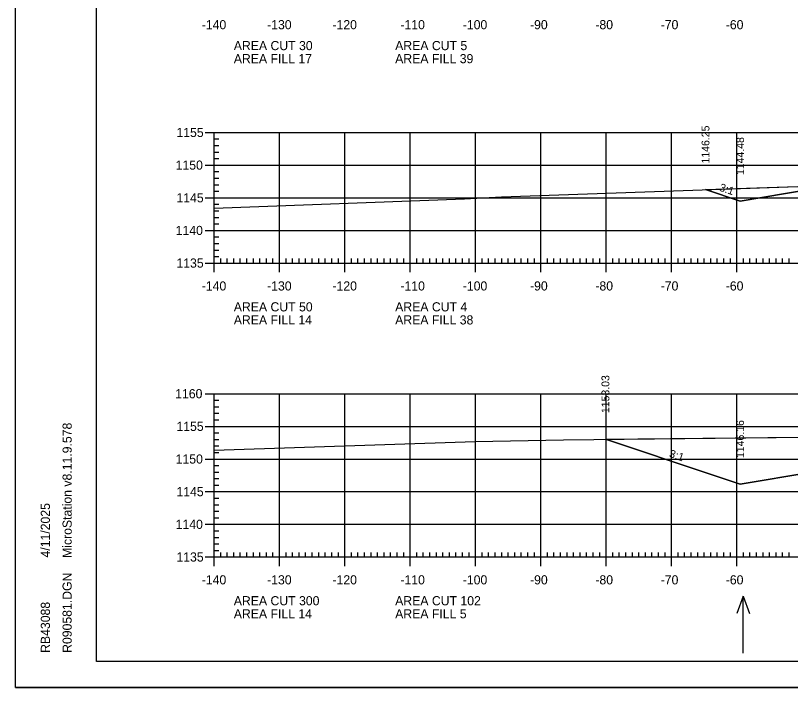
# Model space of a CAD drawing. Extents: x 1322838 to 1324533, y 339903 to 351025.
# Drawn here: x 1323533.3 to 1323651.9, y 342676.5 to 342779.4 of the extents above; entities that cross this region are included whole.
import ezdxf

# ---------------------------------------------------------------- set-up
doc = ezdxf.new("R2010")
doc.units = 0
for name, color, linetype in [('R_Axis', 7, 'Continuous'), ('R_Axis Annot', 7, 'Continuous'), ('R_Border', 7, 'Continuous'), ('R_Exist Surface', 7, 'Continuous'), ('R_Fin Surface', 7, 'Continuous'), ('R_Fin Surface Annot', 7, 'Continuous'), ('R_Grid', 7, 'Continuous'), ('R_No Plot', 7, 'Continuous'), ('R_Water Annot', 7, 'Continuous')]:
    doc.layers.add(name, color=color, linetype=linetype)

msp = doc.modelspace()

# ---------------------------------------------------------------- linework, layer by layer
at = {"layer": 'R_Axis'}
for p, q in [((1323562.32, 342761.5), (1323565.12, 342761.5)), ((1323563.72, 342741.5), (1323563.72, 342761.5)), ((1323563.72, 342760.5), (1323564.42, 342760.5)), ((1323563.72, 342759.5), (1323564.42, 342759.5)), ((1323563.72, 342758.5), (1323564.42, 342758.5)), ((1323563.72, 342757.5), (1323564.42, 342757.5)), ((1323562.32, 342756.5), (1323565.12, 342756.5)), ((1323563.72, 342755.5), (1323564.42, 342755.5)), ((1323563.72, 342754.5), (1323564.42, 342754.5)), ((1323563.72, 342753.5), (1323564.42, 342753.5)), ((1323563.72, 342752.5), (1323564.42, 342752.5)), ((1323562.32, 342751.5), (1323565.12, 342751.5)), ((1323563.72, 342750.5), (1323564.42, 342750.5)), ((1323563.72, 342749.5), (1323564.42, 342749.5)), ((1323563.72, 342748.5), (1323564.42, 342748.5)), ((1323562.32, 342746.5), (1323565.12, 342746.5)), ((1323563.72, 342747.5), (1323564.42, 342747.5)), ((1323563.72, 342745.5), (1323564.42, 342745.5)), ((1323563.72, 342744.5), (1323564.42, 342744.5)), ((1323563.72, 342743.5), (1323564.42, 342743.5)), ((1323563.72, 342740.1), (1323563.72, 342742.9)), ((1323573.72, 342740.1), (1323573.72, 342742.9)), ((1323583.72, 342740.1), (1323583.72, 342742.9)), ((1323593.72, 342740.1), (1323593.72, 342742.9)), ((1323603.72, 342740.1), (1323603.72, 342742.9)), ((1323613.72, 342740.1), (1323613.72, 342742.9)), ((1323623.72, 342740.1), (1323623.72, 342742.9)), ((1323633.72, 342740.1), (1323633.72, 342742.9)), ((1323643.72, 342740.1), (1323643.72, 342742.9)), ((1323563.72, 342742.5), (1323564.42, 342742.5)), ((1323564.72, 342741.5), (1323564.72, 342742.2)), ((1323565.72, 342741.5), (1323565.72, 342742.2)), ((1323566.72, 342741.5), (1323566.72, 342742.2)), ((1323567.72, 342741.5), (1323567.72, 342742.2)), ((1323568.72, 342741.5), (1323568.72, 342742.2)), ((1323569.72, 342741.5), (1323569.72, 342742.2)), ((1323570.72, 342741.5), (1323570.72, 342742.2)), ((1323571.72, 342741.5), (1323571.72, 342742.2)), ((1323572.72, 342741.5), (1323572.72, 342742.2)), ((1323574.72, 342741.5), (1323574.72, 342742.2)), ((1323575.72, 342741.5), (1323575.72, 342742.2)), ((1323576.72, 342741.5), (1323576.72, 342742.2)), ((1323577.72, 342741.5), (1323577.72, 342742.2)), ((1323578.72, 342741.5), (1323578.72, 342742.2)), ((1323579.72, 342741.5), (1323579.72, 342742.2)), ((1323580.72, 342741.5), (1323580.72, 342742.2)), ((1323581.72, 342741.5), (1323581.72, 342742.2)), ((1323582.72, 342741.5), (1323582.72, 342742.2)), ((1323584.72, 342741.5), (1323584.72, 342742.2)), ((1323585.72, 342741.5), (1323585.72, 342742.2)), ((1323586.72, 342741.5), (1323586.72, 342742.2)), ((1323587.72, 342741.5), (1323587.72, 342742.2)), ((1323588.72, 342741.5), (1323588.72, 342742.2)), ((1323589.72, 342741.5), (1323589.72, 342742.2)), ((1323590.72, 342741.5), (1323590.72, 342742.2)), ((1323591.72, 342741.5), (1323591.72, 342742.2)), ((1323592.72, 342741.5), (1323592.72, 342742.2)), ((1323594.72, 342741.5), (1323594.72, 342742.2)), ((1323595.72, 342741.5), (1323595.72, 342742.2)), ((1323596.72, 342741.5), (1323596.72, 342742.2)), ((1323597.72, 342741.5), (1323597.72, 342742.2)), ((1323598.72, 342741.5), (1323598.72, 342742.2)), ((1323599.72, 342741.5), (1323599.72, 342742.2)), ((1323600.72, 342741.5), (1323600.72, 342742.2)), ((1323601.72, 342741.5), (1323601.72, 342742.2)), ((1323602.72, 342741.5), (1323602.72, 342742.2)), ((1323604.72, 342741.5), (1323604.72, 342742.2)), ((1323605.72, 342741.5), (1323605.72, 342742.2)), ((1323606.72, 342741.5), (1323606.72, 342742.2)), ((1323607.72, 342741.5), (1323607.72, 342742.2)), ((1323608.72, 342741.5), (1323608.72, 342742.2)), ((1323609.72, 342741.5), (1323609.72, 342742.2)), ((1323610.72, 342741.5), (1323610.72, 342742.2)), ((1323611.72, 342741.5), (1323611.72, 342742.2)), ((1323612.72, 342741.5), (1323612.72, 342742.2)), ((1323614.72, 342741.5), (1323614.72, 342742.2)), ((1323615.72, 342741.5), (1323615.72, 342742.2)), ((1323616.72, 342741.5), (1323616.72, 342742.2)), ((1323617.72, 342741.5), (1323617.72, 342742.2)), ((1323618.72, 342741.5), (1323618.72, 342742.2)), ((1323619.72, 342741.5), (1323619.72, 342742.2)), ((1323620.72, 342741.5), (1323620.72, 342742.2)), ((1323621.72, 342741.5), (1323621.72, 342742.2)), ((1323622.72, 342741.5), (1323622.72, 342742.2)), ((1323624.72, 342741.5), (1323624.72, 342742.2)), ((1323625.72, 342741.5), (1323625.72, 342742.2)), ((1323626.72, 342741.5), (1323626.72, 342742.2)), ((1323627.72, 342741.5), (1323627.72, 342742.2)), ((1323628.72, 342741.5), (1323628.72, 342742.2)), ((1323629.72, 342741.5), (1323629.72, 342742.2)), ((1323630.72, 342741.5), (1323630.72, 342742.2)), ((1323631.72, 342741.5), (1323631.72, 342742.2)), ((1323632.72, 342741.5), (1323632.72, 342742.2)), ((1323634.72, 342741.5), (1323634.72, 342742.2)), ((1323635.72, 342741.5), (1323635.72, 342742.2)), ((1323636.72, 342741.5), (1323636.72, 342742.2)), ((1323637.72, 342741.5), (1323637.72, 342742.2)), ((1323638.72, 342741.5), (1323638.72, 342742.2)), ((1323639.72, 342741.5), (1323639.72, 342742.2)), ((1323640.72, 342741.5), (1323640.72, 342742.2)), ((1323641.72, 342741.5), (1323641.72, 342742.2)), ((1323642.72, 342741.5), (1323642.72, 342742.2)), ((1323644.72, 342741.5), (1323644.72, 342742.2)), ((1323645.72, 342741.5), (1323645.72, 342742.2)), ((1323646.72, 342741.5), (1323646.72, 342742.2)), ((1323647.72, 342741.5), (1323647.72, 342742.2)), ((1323648.72, 342741.5), (1323648.72, 342742.2)), ((1323649.72, 342741.5), (1323649.72, 342742.2)), ((1323650.72, 342741.5), (1323650.72, 342742.2)), ((1323651.72, 342741.5), (1323651.72, 342742.2)), ((1323562.32, 342741.5), (1323565.12, 342741.5)), ((1323563.72, 342741.5), (1323843.72, 342741.5)), ((1323562.32, 342721.5), (1323565.12, 342721.5)), ((1323563.72, 342696.5), (1323563.72, 342721.5)), ((1323563.72, 342720.5), (1323564.42, 342720.5)), ((1323563.72, 342719.5), (1323564.42, 342719.5)), ((1323563.72, 342718.5), (1323564.42, 342718.5)), ((1323563.72, 342717.5), (1323564.42, 342717.5)), ((1323562.32, 342716.5), (1323565.12, 342716.5)), ((1323563.72, 342715.5), (1323564.42, 342715.5)), ((1323563.72, 342714.5), (1323564.42, 342714.5)), ((1323563.72, 342713.5), (1323564.42, 342713.5)), ((1323563.72, 342712.5), (1323564.42, 342712.5)), ((1323562.32, 342711.5), (1323565.12, 342711.5)), ((1323563.72, 342710.5), (1323564.42, 342710.5)), ((1323563.72, 342709.5), (1323564.42, 342709.5)), ((1323563.72, 342708.5), (1323564.42, 342708.5)), ((1323563.72, 342707.5), (1323564.42, 342707.5)), ((1323562.32, 342706.5), (1323565.12, 342706.5)), ((1323563.72, 342705.5), (1323564.42, 342705.5)), ((1323563.72, 342704.5), (1323564.42, 342704.5)), ((1323563.72, 342703.5), (1323564.42, 342703.5)), ((1323562.32, 342701.5), (1323565.12, 342701.5)), ((1323563.72, 342702.5), (1323564.42, 342702.5)), ((1323563.72, 342700.5), (1323564.42, 342700.5)), ((1323563.72, 342699.5), (1323564.42, 342699.5)), ((1323563.72, 342698.5), (1323564.42, 342698.5)), ((1323563.72, 342695.1), (1323563.72, 342697.9)), ((1323573.72, 342695.1), (1323573.72, 342697.9)), ((1323583.72, 342695.1), (1323583.72, 342697.9)), ((1323593.72, 342695.1), (1323593.72, 342697.9)), ((1323603.72, 342695.1), (1323603.72, 342697.9)), ((1323613.72, 342695.1), (1323613.72, 342697.9)), ((1323623.72, 342695.1), (1323623.72, 342697.9)), ((1323633.72, 342695.1), (1323633.72, 342697.9)), ((1323643.72, 342695.1), (1323643.72, 342697.9)), ((1323563.72, 342697.5), (1323564.42, 342697.5)), ((1323564.72, 342696.5), (1323564.72, 342697.2)), ((1323565.72, 342696.5), (1323565.72, 342697.2)), ((1323566.72, 342696.5), (1323566.72, 342697.2)), ((1323567.72, 342696.5), (1323567.72, 342697.2)), ((1323568.72, 342696.5), (1323568.72, 342697.2)), ((1323569.72, 342696.5), (1323569.72, 342697.2)), ((1323570.72, 342696.5), (1323570.72, 342697.2)), ((1323571.72, 342696.5), (1323571.72, 342697.2)), ((1323572.72, 342696.5), (1323572.72, 342697.2)), ((1323574.72, 342696.5), (1323574.72, 342697.2)), ((1323575.72, 342696.5), (1323575.72, 342697.2)), ((1323576.72, 342696.5), (1323576.72, 342697.2)), ((1323577.72, 342696.5), (1323577.72, 342697.2)), ((1323578.72, 342696.5), (1323578.72, 342697.2)), ((1323579.72, 342696.5), (1323579.72, 342697.2)), ((1323580.72, 342696.5), (1323580.72, 342697.2)), ((1323581.72, 342696.5), (1323581.72, 342697.2)), ((1323582.72, 342696.5), (1323582.72, 342697.2)), ((1323584.72, 342696.5), (1323584.72, 342697.2)), ((1323585.72, 342696.5), (1323585.72, 342697.2)), ((1323586.72, 342696.5), (1323586.72, 342697.2)), ((1323587.72, 342696.5), (1323587.72, 342697.2)), ((1323588.72, 342696.5), (1323588.72, 342697.2)), ((1323589.72, 342696.5), (1323589.72, 342697.2)), ((1323590.72, 342696.5), (1323590.72, 342697.2)), ((1323591.72, 342696.5), (1323591.72, 342697.2)), ((1323592.72, 342696.5), (1323592.72, 342697.2)), ((1323594.72, 342696.5), (1323594.72, 342697.2)), ((1323595.72, 342696.5), (1323595.72, 342697.2)), ((1323596.72, 342696.5), (1323596.72, 342697.2)), ((1323597.72, 342696.5), (1323597.72, 342697.2)), ((1323598.72, 342696.5), (1323598.72, 342697.2)), ((1323599.72, 342696.5), (1323599.72, 342697.2)), ((1323600.72, 342696.5), (1323600.72, 342697.2)), ((1323601.72, 342696.5), (1323601.72, 342697.2)), ((1323602.72, 342696.5), (1323602.72, 342697.2)), ((1323604.72, 342696.5), (1323604.72, 342697.2)), ((1323605.72, 342696.5), (1323605.72, 342697.2)), ((1323606.72, 342696.5), (1323606.72, 342697.2)), ((1323607.72, 342696.5), (1323607.72, 342697.2)), ((1323608.72, 342696.5), (1323608.72, 342697.2)), ((1323609.72, 342696.5), (1323609.72, 342697.2)), ((1323610.72, 342696.5), (1323610.72, 342697.2)), ((1323611.72, 342696.5), (1323611.72, 342697.2)), ((1323612.72, 342696.5), (1323612.72, 342697.2)), ((1323614.72, 342696.5), (1323614.72, 342697.2)), ((1323615.72, 342696.5), (1323615.72, 342697.2)), ((1323616.72, 342696.5), (1323616.72, 342697.2)), ((1323617.72, 342696.5), (1323617.72, 342697.2)), ((1323618.72, 342696.5), (1323618.72, 342697.2)), ((1323619.72, 342696.5), (1323619.72, 342697.2)), ((1323620.72, 342696.5), (1323620.72, 342697.2)), ((1323621.72, 342696.5), (1323621.72, 342697.2)), ((1323622.72, 342696.5), (1323622.72, 342697.2)), ((1323624.72, 342696.5), (1323624.72, 342697.2)), ((1323625.72, 342696.5), (1323625.72, 342697.2)), ((1323626.72, 342696.5), (1323626.72, 342697.2)), ((1323627.72, 342696.5), (1323627.72, 342697.2)), ((1323628.72, 342696.5), (1323628.72, 342697.2)), ((1323629.72, 342696.5), (1323629.72, 342697.2)), ((1323630.72, 342696.5), (1323630.72, 342697.2)), ((1323631.72, 342696.5), (1323631.72, 342697.2)), ((1323632.72, 342696.5), (1323632.72, 342697.2)), ((1323634.72, 342696.5), (1323634.72, 342697.2)), ((1323635.72, 342696.5), (1323635.72, 342697.2)), ((1323636.72, 342696.5), (1323636.72, 342697.2)), ((1323637.72, 342696.5), (1323637.72, 342697.2)), ((1323638.72, 342696.5), (1323638.72, 342697.2)), ((1323639.72, 342696.5), (1323639.72, 342697.2)), ((1323640.72, 342696.5), (1323640.72, 342697.2)), ((1323641.72, 342696.5), (1323641.72, 342697.2)), ((1323642.72, 342696.5), (1323642.72, 342697.2)), ((1323644.72, 342696.5), (1323644.72, 342697.2)), ((1323645.72, 342696.5), (1323645.72, 342697.2)), ((1323646.72, 342696.5), (1323646.72, 342697.2)), ((1323647.72, 342696.5), (1323647.72, 342697.2)), ((1323648.72, 342696.5), (1323648.72, 342697.2)), ((1323649.72, 342696.5), (1323649.72, 342697.2)), ((1323650.72, 342696.5), (1323650.72, 342697.2)), ((1323651.72, 342696.5), (1323651.72, 342697.2)), ((1323562.32, 342696.5), (1323565.12, 342696.5)), ((1323563.72, 342696.5), (1323843.72, 342696.5))]:
    msp.add_line(p, q, dxfattribs=at)
at = {"layer": 'R_Border'}
for p, q in [((1323545.72, 342680.5), (1323545.72, 342885.96)), ((1323545.72, 342680.5), (1323545.72, 342680.5)), ((1323861.9, 342680.5), (1323545.72, 342680.5))]:
    msp.add_line(p, q, dxfattribs=at)
at = {"layer": 'R_Exist Surface'}
for points in [[(1323563.72, 342749.92), (1323602.04, 342751.35), (1323607.67, 342751.65), (1323653.03, 342753.24)], [(1323563.72, 342712.87), (1323603.64, 342714.19), (1323617.19, 342714.46), (1323668.28, 342715.01)]]:
    msp.add_lwpolyline(points, dxfattribs=at)
at = {"layer": 'R_Fin Surface'}
for points in [[(1323638.92, 342752.75), (1323644.22, 342750.98), (1323654.77, 342752.74), (1323654.78, 342752.74), (1323666.21, 342754.65), (1323666.22, 342754.65), (1323672.21, 342754.38), (1323672.22, 342754.38), (1323674.22, 342754.29), (1323703.71, 342752.99), (1323703.72, 342752.99), (1323733.21, 342751.68), (1323733.22, 342751.68), (1323735.22, 342751.59), (1323735.22, 342751.59), (1323741.22, 342751.33), (1323741.22, 342751.46), (1323741.23, 342751.49), (1323741.98, 342751.83), (1323741.98, 342751.83), (1323749.22, 342752.08), (1323763.2, 342752.57)], [(1323623.6, 342714.53), (1323639.65, 342709.18), (1323644.22, 342707.65), (1323655.19, 342709.48), (1323664.17, 342710.98), (1323666.21, 342711.32), (1323667.75, 342711.27), (1323672.21, 342711.12), (1323674.21, 342711.05), (1323688.15, 342710.57), (1323703.72, 342710.04), (1323733.22, 342709.04), (1323734, 342709.01), (1323735.22, 342708.97), (1323740.07, 342708.77), (1323741.22, 342708.73), (1323749.97, 342707.27), (1323763.22, 342705.06), (1323781.49, 342711.15)]]:
    msp.add_lwpolyline(points, dxfattribs=at)
at = {"layer": 'R_Grid'}
for p, q in [((1323563.72, 342761.5), (1323843.72, 342761.5)), ((1323563.72, 342741.5), (1323563.72, 342761.5)), ((1323573.72, 342741.5), (1323573.72, 342761.5)), ((1323583.72, 342741.5), (1323583.72, 342761.5)), ((1323593.72, 342741.5), (1323593.72, 342761.5)), ((1323603.72, 342741.5), (1323603.72, 342761.5)), ((1323613.72, 342741.5), (1323613.72, 342761.5)), ((1323623.72, 342741.5), (1323623.72, 342761.5)), ((1323633.72, 342741.5), (1323633.72, 342761.5)), ((1323643.72, 342741.5), (1323643.72, 342761.5)), ((1323563.72, 342756.5), (1323843.72, 342756.5)), ((1323563.72, 342751.5), (1323843.72, 342751.5)), ((1323563.72, 342746.5), (1323843.72, 342746.5)), ((1323563.72, 342741.5), (1323843.72, 342741.5)), ((1323563.72, 342721.5), (1323843.72, 342721.5)), ((1323563.72, 342696.5), (1323563.72, 342721.5)), ((1323573.72, 342696.5), (1323573.72, 342721.5)), ((1323583.72, 342696.5), (1323583.72, 342721.5)), ((1323593.72, 342696.5), (1323593.72, 342721.5)), ((1323603.72, 342696.5), (1323603.72, 342721.5)), ((1323613.72, 342696.5), (1323613.72, 342721.5)), ((1323623.72, 342696.5), (1323623.72, 342721.5)), ((1323633.72, 342696.5), (1323633.72, 342721.5)), ((1323643.72, 342696.5), (1323643.72, 342721.5)), ((1323563.72, 342716.5), (1323843.72, 342716.5)), ((1323563.72, 342711.5), (1323843.72, 342711.5)), ((1323563.72, 342706.5), (1323843.72, 342706.5)), ((1323563.72, 342701.5), (1323843.72, 342701.5)), ((1323563.72, 342696.5), (1323843.72, 342696.5))]:
    msp.add_line(p, q, dxfattribs=at)
at = {"layer": 'R_No Plot'}
msp.add_line((1323533.31, 342676.52), (1323866.65, 342676.52), dxfattribs=at)
for points in [[(1323533.31, 342889.85), (1323866.65, 342889.85), (1323866.65, 342676.51), (1323533.31, 342676.51)], [(1323779.64, 342885.96), (1323799.26, 342885.96), (1323799.26, 342876.08), (1323815.37, 342876.08), (1323838.57, 342876.08), (1323838.57, 342843.41), (1323861.77, 342843.41), (1323861.9, 342680.5), (1323545.72, 342680.5), (1323545.72, 342885.96)], [(1323638.92, 342752.75), (1323653.03, 342753.24), (1323669.08, 342753.8), (1323678.21, 342754.12), (1323684.64, 342754.39), (1323690.43, 342752.28), (1323672.22, 342753.09), (1323654.78, 342752.74), (1323654.77, 342752.74), (1323644.22, 342750.98), (1323638.92, 342752.75)], [(1323623.6, 342714.53), (1323668.28, 342715.01), (1323673.55, 342715.11), (1323679.28, 342715.16), (1323682.85, 342713.24), (1323686.62, 342711.23), (1323690.74, 342709.19), (1323672.21, 342709.82), (1323655.19, 342709.48), (1323644.22, 342707.65), (1323639.65, 342709.18), (1323623.6, 342714.53)]]:
    msp.add_lwpolyline(points, close=True, dxfattribs=at)
at = {"layer": 'R_Water Annot'}
for p, q in [((1323644.66, 342690.48), (1323643.69, 342687.82)), ((1323644.66, 342681.79), (1323644.66, 342690.48)), ((1323644.66, 342690.48), (1323645.63, 342687.82))]:
    msp.add_line(p, q, dxfattribs=at)

# ---------------------------------------------------------------- texts
at = {"layer": 'R_Axis Annot'}
for s, p in [('-140', (1323561.82, 342777.3)), ('-130', (1323571.82, 342777.3)), ('-120', (1323581.82, 342777.3)), ('-110', (1323592.22, 342777.3)), ('-100', (1323601.77, 342777.3)), ('-90', (1323612.06, 342777.3)), ('-80', (1323622.06, 342777.3)), ('-70', (1323632.06, 342777.3)), ('-60', (1323642.02, 342777.3)), ('AREA CUT 30', (1323566.72, 342774.1)), ('AREA CUT 5', (1323591.42, 342774.1)), ('AREA FILL 17', (1323566.72, 342772.1)), ('AREA FILL 39', (1323591.42, 342772.1)), ('1155', (1323557.94, 342760.8)), ('1150', (1323557.82, 342755.8)), ('1145', (1323557.94, 342750.8)), ('1140', (1323557.82, 342745.8)), ('1135', (1323557.94, 342740.8)), ('-140', (1323561.82, 342737.3)), ('-130', (1323571.82, 342737.3)), ('-120', (1323581.82, 342737.3)), ('-110', (1323592.22, 342737.3)), ('-100', (1323601.77, 342737.3)), ('-90', (1323612.06, 342737.3)), ('-80', (1323622.06, 342737.3)), ('-70', (1323632.06, 342737.3)), ('-60', (1323642.02, 342737.3)), ('AREA CUT 50', (1323566.72, 342734.1)), ('AREA CUT 4', (1323591.42, 342734.1)), ('AREA FILL 14', (1323566.72, 342732.1)), ('AREA FILL 38', (1323591.42, 342732.1)), ('1160', (1323557.75, 342720.8)), ('1155', (1323557.94, 342715.8)), ('1150', (1323557.82, 342710.8)), ('1145', (1323557.94, 342705.8)), ('1140', (1323557.82, 342700.8)), ('1135', (1323557.94, 342695.8)), ('-140', (1323561.82, 342692.3)), ('-130', (1323571.82, 342692.3)), ('-120', (1323581.82, 342692.3)), ('-110', (1323592.22, 342692.3)), ('-100', (1323601.77, 342692.3)), ('-90', (1323612.06, 342692.3)), ('-80', (1323622.06, 342692.3)), ('-70', (1323632.06, 342692.3)), ('-60', (1323642.02, 342692.3)), ('AREA CUT 300', (1323566.72, 342689.1)), ('AREA CUT 102', (1323591.42, 342689.1)), ('AREA FILL 14', (1323566.72, 342687.1)), ('AREA FILL 5', (1323591.42, 342687.1))]:
    msp.add_text(s, height=1.4, dxfattribs=at).set_placement(p)
at = {"layer": 'R_Border'}
for s, p in [('MicroStation v8.11.9.578', (1323541.91, 342696.35)), ('4/11/2025', (1323538.58, 342696.42)), ('R090581.DGN', (1323541.91, 342681.82)), ('RB43088', (1323538.58, 342681.82))]:
    msp.add_text(s, height=1.4, rotation=90, dxfattribs=at).set_placement(p)
at = {"layer": 'R_Fin Surface Annot'}
for s, rotation, p in [('1146.25', 90, (1323639.52, 342756.75)), ('1144.48', 90, (1323644.82, 342754.98)), ('3:1', 341.5592, (1323640.94, 342752.6)), ('1153.03', 90, (1323624.2, 342718.53)), ('1146.16', 90, (1323644.82, 342711.65)), ('3:1', 341.5634, (1323633.28, 342711.83))]:
    msp.add_text(s, height=1.2, rotation=rotation, dxfattribs=at).set_placement(p)

doc.saveas('drawing.dxf')
